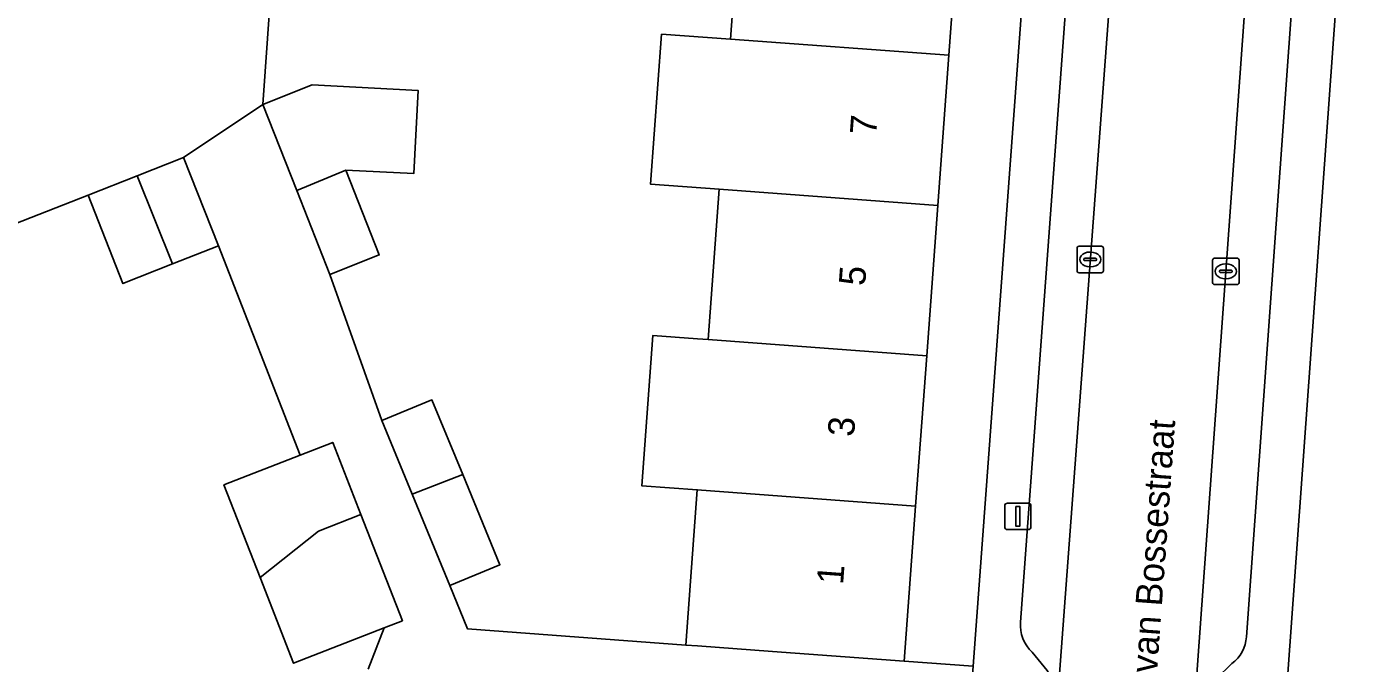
# Model space of a CAD drawing. Extents: x 160304 to 160955, y 383684 to 384161.
# Drawn here: x 160474.6 to 160524.56, y 383949.15 to 383973.25 of the extents above; entities that cross this region are included whole.
import ezdxf

# ---------------------------------------------------------------- set-up
doc = ezdxf.new("R2010")
doc.units = 0
for name, color, linetype in [('IMGEO_Erf', 7, 'Continuous'), ('IMGEO_Kolk', 7, 'Continuous'), ('IMGEO_Lichtmast', 7, 'Continuous'), ('IMGEO_Openbare_ruimte_label', 7, 'Continuous'), ('IMGEO_Pand', 7, 'Continuous'), ('IMGEO_Pand_nummerreeks', 7, 'Continuous'), ('IMGEO_Parkeervlak_open', 7, 'Continuous'), ('IMGEO_Rijbaan_lokaal_open', 7, 'Continuous'), ('IMGEO_Voetpad_open', 7, 'Continuous')]:
    doc.layers.add(name, color=color, linetype=linetype)

msp = doc.modelspace()

# ---------------------------------------------------------------- linework, layer by layer
at = {"layer": 'IMGEO_Erf'}
for points in [[(160514.187, 384000), (160514.205, 384000.248), (160511.589, 384000.441), (160511.557, 384000), (160511.181, 383994.892), (160510.762, 383989.202), (160510.343, 383983.504), (160509.925, 383977.831), (160509.508, 383972.165), (160509.089, 383966.47), (160508.671, 383960.787), (160508.253, 383955.106), (160507.821, 383949.239), (160510.426, 383949.047)], [(160527.389, 383982.34), (160527.806, 383988.006), (160528.225, 383993.695), (160528.645, 383999.401), (160525.998, 383999.592), (160522.302, 383948.238), (160524.866, 383948.053), (160525.298, 383953.917), (160525.715, 383959.593), (160526.134, 383965.285), (160526.553, 383970.972), (160526.971, 383976.651)]]:
    msp.add_lwpolyline(points, close=True, dxfattribs=at)
for points in [[(160483.805, 383974.048), (160483.543, 383970.297), (160485.416, 383971.037), (160489.419, 383970.832), (160489.258, 383967.683), (160486.687, 383967.815), (160487.953, 383964.606), (160486.08, 383963.867), (160488.044, 383958.338), (160489.945, 383959.123), (160491.11, 383956.301), (160492.519, 383952.887), (160490.618, 383952.102), (160491.297, 383950.456), (160499.552, 383949.848), (160499.984, 383955.719), (160497.886, 383955.873), (160498.304, 383961.554), (160500, 383961.429), (160500.402, 383961.4), (160500.821, 383967.09), (160498.214, 383967.285), (160498.639, 383972.956), (160501.239, 383972.77), (160501.658, 383978.45)], [(160487.538, 383948.928), (160488.135, 383950.497), (160484.711, 383949.158), (160483.442, 383952.404), (160482.073, 383955.904), (160484.963, 383957.035), (160481.867, 383964.95), (160480.132, 383964.265), (160478.253, 383963.524), (160476.935, 383966.864), (160474.132, 383965.766)]]:
    msp.add_lwpolyline(points, dxfattribs=at)
at = {"layer": 'IMGEO_Kolk'}
for p, q in [((160514.36, 383964.008), (160514.36, 383964.86)), ((160514.435, 383964.934), (160515.287, 383964.934)), ((160515.361, 383964.86), (160515.361, 383964.008)), ((160514.619, 383964.428), (160514.619, 383964.44)), ((160515.057, 383964.391), (160514.659, 383964.391)), ((160514.662, 383964.477), (160515.06, 383964.477)), ((160514.848, 383964.714), (160514.873, 383964.714)), ((160515.103, 383964.44), (160515.103, 383964.428)), ((160519.491, 383963.558), (160519.491, 383964.41)), ((160519.566, 383964.484), (160520.418, 383964.484)), ((160520.492, 383964.41), (160520.492, 383963.558)), ((160515.287, 383963.934), (160514.435, 383963.934)), ((160514.871, 383964.154), (160514.846, 383964.154)), ((160519.75, 383963.978), (160519.75, 383963.99)), ((160520.188, 383963.941), (160519.79, 383963.941)), ((160519.793, 383964.027), (160520.191, 383964.027)), ((160519.979, 383964.264), (160520.004, 383964.264)), ((160520.234, 383963.99), (160520.234, 383963.978)), ((160520.418, 383963.484), (160519.566, 383963.484)), ((160520.002, 383963.704), (160519.977, 383963.704))]:
    msp.add_line(p, q, dxfattribs=at)
for points in [[(160514.36, 383964.008), (160514.36, 383964.86)], [(160514.435, 383964.934), (160515.287, 383964.934)], [(160515.361, 383964.86), (160515.361, 383964.008)], [(160519.491, 383963.558), (160519.491, 383964.41)], [(160519.566, 383964.484), (160520.418, 383964.484)], [(160520.492, 383964.41), (160520.492, 383963.558)], [(160515.287, 383963.934), (160514.435, 383963.934)], [(160520.418, 383963.484), (160519.566, 383963.484)]]:
    msp.add_lwpolyline(points, dxfattribs=at)
for centre, radius, start, end in [((160514.437, 383964.858), 0.0765, 91.552, 178.448), ((160514.437, 383964.858), 0.0765, 91.552, 178.448), ((160515.285, 383964.858), 0.0765, 1.552, 88.448), ((160515.285, 383964.858), 0.0765, 1.552, 88.448), ((160514.659, 383964.437), 0.0403, 85.8775, 175.7526), ((160514.656, 383964.427), 0.0366, 178.938, 274.7102), ((160515.06, 383964.434), 0.043, 264.8664, 352.4533), ((160515.064, 383964.439), 0.0386, 1.7309, 96.639), ((160519.568, 383964.408), 0.0765, 91.552, 178.448), ((160519.568, 383964.408), 0.0765, 91.552, 178.448), ((160520.416, 383964.408), 0.0765, 1.552, 88.448), ((160520.416, 383964.408), 0.0765, 1.552, 88.448), ((160514.437, 383964.01), 0.0765, 181.552, 268.448), ((160514.437, 383964.01), 0.0765, 181.552, 268.448), ((160515.285, 383964.01), 0.0765, 271.552, 358.448), ((160515.285, 383964.01), 0.0765, 271.552, 358.448), ((160519.79, 383963.987), 0.0403, 85.8775, 175.7526), ((160519.787, 383963.977), 0.0366, 178.938, 274.7102), ((160520.191, 383963.984), 0.043, 264.8664, 352.4533), ((160520.195, 383963.989), 0.0386, 1.7309, 96.639), ((160519.568, 383963.56), 0.0765, 181.552, 268.448), ((160519.568, 383963.56), 0.0765, 181.552, 268.448), ((160520.416, 383963.56), 0.0765, 271.552, 358.448), ((160520.416, 383963.56), 0.0765, 271.552, 358.448)]:
    msp.add_arc(centre, radius, start, end, dxfattribs=at)
for centre, major_axis, ratio, start_param, end_param in [((160514.847, 383964.434), (-0.387, 0.002), 0.722429, 4.712389, 7.853982), ((160514.872, 383964.434), (-0.39, 0.002), 0.717154, 1.570796, 4.712389), ((160519.978, 383963.984), (-0.387, 0.002), 0.722429, 4.712389, 7.853982), ((160520.003, 383963.984), (-0.39, 0.002), 0.717154, 1.570796, 4.712389)]:
    msp.add_ellipse(centre, major_axis=major_axis, ratio=ratio, start_param=start_param, end_param=end_param, dxfattribs=at)
at = {"layer": 'IMGEO_Lichtmast'}
for p, q in [((160511.625, 383954.315), (160511.625, 383955.115)), ((160511.625, 383955.115), (160511.625, 383954.315)), ((160511.725, 383955.215), (160512.515, 383955.215)), ((160512.515, 383955.215), (160511.725, 383955.215)), ((160512.615, 383955.115), (160512.615, 383954.315)), ((160512.615, 383954.315), (160512.615, 383955.115)), ((160512.515, 383954.215), (160511.725, 383954.215)), ((160511.725, 383954.215), (160512.515, 383954.215))]:
    msp.add_line(p, q, dxfattribs=at)
msp.add_lwpolyline([(160512.045, 383955.09), (160512.195, 383955.09), (160512.195, 383954.34), (160512.045, 383954.34), (160512.045, 383955.09)], dxfattribs=at)
for centre, start, end in [((160511.725, 383955.115), 90, 180), ((160511.725, 383955.115), 90, 180), ((160512.515, 383955.115), 0, 90), ((160512.515, 383955.115), 360, 90), ((160511.725, 383954.315), 180, 270), ((160511.725, 383954.315), 180, 270), ((160512.515, 383954.315), 270, 0), ((160512.515, 383954.315), 270, 0)]:
    msp.add_arc(centre, 0.1, start, end, dxfattribs=at)
at = {"layer": 'IMGEO_Pand'}
for points in [[(160501.239, 383972.77), (160509.508, 383972.165), (160509.925, 383977.831), (160501.658, 383978.45)], [(160501.239, 383972.77), (160498.639, 383972.956), (160498.214, 383967.285), (160500.821, 383967.09), (160509.089, 383966.47), (160509.508, 383972.165)], [(160484.829, 383967.038), (160486.687, 383967.815), (160489.258, 383967.683), (160489.419, 383970.832), (160485.416, 383971.037), (160483.543, 383970.297)], [(160478.795, 383967.598), (160480.132, 383964.265), (160481.867, 383964.95), (160480.549, 383968.29)], [(160484.829, 383967.038), (160486.08, 383963.867), (160487.953, 383964.606), (160486.687, 383967.815)], [(160478.795, 383967.598), (160476.935, 383966.864), (160478.253, 383963.524), (160480.132, 383964.265)], [(160500.402, 383961.4), (160508.671, 383960.787), (160509.089, 383966.47), (160500.821, 383967.09)], [(160500.402, 383961.4), (160500, 383961.429), (160498.304, 383961.554), (160497.886, 383955.873), (160499.984, 383955.719), (160508.253, 383955.106), (160508.671, 383960.787)], [(160489.195, 383955.549), (160491.11, 383956.301), (160489.945, 383959.123), (160488.044, 383958.338)], [(160486.189, 383957.514), (160484.963, 383957.035), (160482.073, 383955.904), (160483.442, 383952.404), (160485.65, 383954.15), (160487.256, 383954.784)], [(160489.195, 383955.549), (160490.618, 383952.102), (160492.519, 383952.887), (160491.11, 383956.301)], [(160508.253, 383955.106), (160499.984, 383955.719), (160499.552, 383949.848), (160500, 383949.815), (160502.835, 383949.607), (160507.821, 383949.239)], [(160487.256, 383954.784), (160485.65, 383954.15), (160483.442, 383952.404), (160484.711, 383949.158), (160488.135, 383950.497), (160488.827, 383950.768)]]:
    msp.add_lwpolyline(points, close=True, dxfattribs=at)
at = {"layer": 'IMGEO_Parkeervlak_open'}
for points in [[(160512.668, 383949.583), (160513.226, 383948.884), (160513.645, 383948.079), (160515.611, 383974.485), (160515.815, 383977.238), (160516.629, 383988.167), (160517.469, 384000), (160517.587, 384001.661)], [(160523.692, 383998.016), (160522.497, 383999.449), (160521.51, 383984.995), (160520.923, 383976.868), (160520.723, 383974.115), (160518.776, 383947.168)], [(160515.771, 383998.911), (160512.225, 383950.713)], [(160520.769, 383950.16), (160524.135, 383996.873)], [(160519.624, 383948.562), (160520.222, 383949.145)]]:
    msp.add_lwpolyline(points, dxfattribs=at)
for centre, radius, start, end in [((160513.531, 383950.573), 1.313, 173.8793, 228.9346), ((160519.406, 383950.239), 1.365, 306.6927, 356.6654)]:
    msp.add_arc(centre, radius, start, end, dxfattribs=at)
at = {"layer": 'IMGEO_Rijbaan_lokaal_open'}
for points in [[(160474.132, 383965.766), (160476.935, 383966.864), (160478.795, 383967.598), (160480.549, 383968.29), (160483.543, 383970.297), (160483.805, 383974.048), (160483.95, 383976.018), (160484.216, 383979.623), (160484.225, 383979.728), (160484.585, 383984.191), (160481.491, 383985.832), (160479.821, 383986.693), (160478.188, 383987.535), (160476.215, 383988.562), (160473.521, 383986.297)], [(160513.781, 383946.923), (160513.493, 383943.035), (160512.117, 383924.431), (160514.451, 383924.257), (160517.105, 383924.059), (160518.455, 383942.738), (160518.729, 383946.518), (160518.776, 383947.168), (160520.723, 383974.115), (160515.611, 383974.485), (160513.645, 383948.079)]]:
    msp.add_lwpolyline(points, dxfattribs=at)
at = {"layer": 'IMGEO_Voetpad_open'}
for points in [[(160518.776, 383947.168), (160518.729, 383946.518), (160519.227, 383946.483), (160518.953, 383942.703), (160518.455, 383942.738), (160517.105, 383924.059), (160518.927, 383923.923), (160519.059, 383925.551), (160519.677, 383933.96), (160519.798, 383935.598), (160519.906, 383937.041), (160520.34, 383942.858), (160520.599, 383946.385), (160522.16, 383946.27), (160522.302, 383948.238), (160525.998, 383999.592), (160526.027, 384000), (160526.157, 384001.805), (160526.404, 384005.17), (160524.792, 384005.245), (160525.428, 384014.213), (160526.037, 384022.511), (160526.375, 384026.574)], [(160514.365, 384002.417), (160514.205, 384000.248), (160514.187, 384000), (160510.426, 383949.047), (160510.279, 383947.055), (160511.901, 383946.936), (160511.647, 383943.484), (160511.009, 383934.527), (160510.393, 383926.169), (160510.274, 383924.568), (160512.117, 383924.431), (160513.493, 383943.035), (160512.995, 383943.072), (160513.283, 383946.96), (160513.781, 383946.923)], [(160512.225, 383950.713), (160515.771, 383998.911)], [(160524.135, 383996.873), (160520.769, 383950.16)], [(160510.426, 383949.047), (160507.821, 383949.239), (160502.835, 383949.607), (160500, 383949.815), (160499.552, 383949.848), (160491.297, 383950.456), (160490.618, 383952.102), (160489.195, 383955.549), (160488.044, 383958.338), (160486.08, 383963.867), (160484.829, 383967.038), (160483.543, 383970.297), (160480.549, 383968.29), (160481.867, 383964.95), (160484.963, 383957.035), (160486.189, 383957.514), (160487.256, 383954.784), (160488.827, 383950.768), (160488.135, 383950.497), (160487.538, 383948.928)], [(160513.645, 383948.079), (160513.226, 383948.884), (160512.668, 383949.583)], [(160520.222, 383949.145), (160519.624, 383948.562)]]:
    msp.add_lwpolyline(points, dxfattribs=at)
for centre, radius, start, end in [((160513.531, 383950.573), 1.313, 173.8793, 228.9346), ((160519.406, 383950.239), 1.365, 306.6927, 356.6654)]:
    msp.add_arc(centre, radius, start, end, dxfattribs=at)

# ---------------------------------------------------------------- texts
at = {"layer": 'IMGEO_Openbare_ruimte_label'}
msp.add_text('Christina Bakker-van Bossestraat', height=1, rotation=85.8695, dxfattribs=at).set_placement((160516.647, 383938.543))
at = {"layer": 'IMGEO_Pand_nummerreeks'}
for s, p in [('7', (160506.758, 383969.122)), ('5', (160506.338, 383963.415)), ('3', (160505.918, 383957.709)), ('1', (160505.506, 383952.116))]:
    msp.add_text(s, height=1, rotation=85.7907, dxfattribs=at).set_placement(p)

doc.saveas('drawing.dxf')
